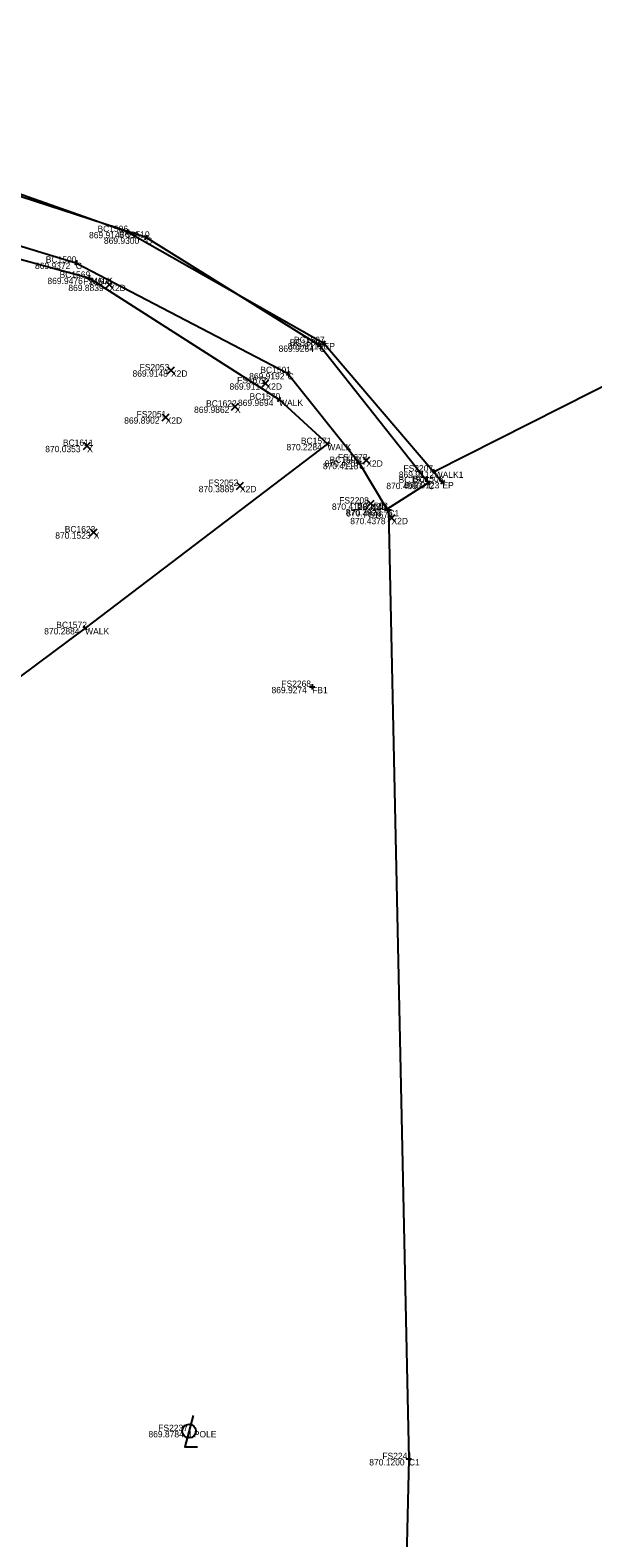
# Model space of a CAD drawing. Extents: x 1479425 to 1480294, y 379351 to 380102.
# Drawn here: x 1479711.18 to 1479716.51, y 379921.85 to 379936.13 of the extents above; entities that cross this region are included whole.
import ezdxf

# ---------------------------------------------------------------- set-up
doc = ezdxf.new("R2010")
doc.units = 0
for name, color, linetype in [('LT_X_Poles', 7, 'Continuous'), ('PV_X_Curb', 7, 'Continuous'), ('PV_X_EOP', 7, 'Continuous'), ('PV_X_Walk', 7, 'Continuous'), ('SV_X_Random_Point', 7, 'Continuous'), ('SV_X_Shot_Marker', 7, 'Continuous'), ('SV_X_Text_Comment', 7, 'Continuous'), ('SV_X_Text_Elevation', 7, 'Continuous'), ('SV_X_Text_Name', 7, 'Continuous')]:
    doc.layers.add(name, color=color, linetype=linetype)

msp = doc.modelspace()

# ---------------------------------------------------------------- linework, layer by layer
at = {"layer": 'LT_X_Poles'}
msp.add_lwpolyline([(1479712.727, 379923.013), (1479712.649, 379922.714), (1479712.767, 379922.714)], dxfattribs=at)
msp.add_circle((1479712.688, 379922.865), 0.065, dxfattribs=at)
at = {"layer": 'PV_X_Curb'}
for points in [[(1479714.562, 379931.597), (1479714.954, 379931.846), (1479713.923, 379933.146), (1479712.281, 379934.169), (1479710.424, 379934.773), (1479708.769, 379934.79), (1479708.11, 379934.798), (1479707.065, 379934.215), (1479706.4, 379933.843), (1479705.682, 379933.059), (1479703.005, 379930.335), (1479700.421, 379927.502), (1479698.116, 379923.793), (1479697.054, 379921.447), (1479696.317, 379919.513), (1479695.811, 379917.681), (1479695.461, 379914.266), (1479695.292, 379911.66), (1479695.283, 379911.471), (1479695.51, 379908.764), (1479695.652, 379906.806)], [(1479696.734, 379903.723), (1479696.078, 379906.871), (1479695.857, 379909.367), (1479695.679, 379911.575), (1479695.63, 379911.718), (1479695.729, 379913.104), (1479695.978, 379915.675), (1479696.198, 379917.494), (1479696.642, 379919.385), (1479697.412, 379921.373), (1479698.591, 379923.939), (1479699.838, 379926.058), (1479700.67, 379927.184), (1479703.372, 379930.269), (1479706.251, 379933.059), (1479706.672, 379933.535), (1479707.045, 379933.739), (1479707.413, 379933.924), (1479708.304, 379934.333), (1479710.149, 379934.374), (1479711.615, 379933.931), (1479713.621, 379932.885), (1479714.299, 379932.035), (1479714.562, 379931.597)], [(1479714.576, 379931.587), (1479714.771, 379922.599), (1479714.229, 379900.013), (1479714.491, 379898.192), (1479715.218, 379896.002), (1479717.036, 379893.796), (1479731.944, 379880.013), (1479745.709, 379867.308), (1479763.187, 379850.751), (1479775.061, 379839.578), (1479781.928, 379833.121), (1479783.777, 379830.713), (1479784.214, 379828.705), (1479783.141, 379825.906)]]:
    msp.add_lwpolyline(points, dxfattribs=at)
at = {"layer": 'PV_X_EOP'}
msp.add_lwpolyline([(1479708.075, 379934.808), (1479710.378, 379934.833), (1479712.105, 379934.222), (1479713.963, 379933.17), (1479715.088, 379931.853)], dxfattribs=at)
at = {"layer": 'PV_X_Walk'}
for points in [[(1479764.347, 379957.039), (1479747.939, 379948.677), (1479730.885, 379939.972), (1479715.015, 379931.953)], [(1479700.819, 379927.207), (1479702.519, 379929.228), (1479704.632, 379931.356), (1479706.478, 379933.039), (1479706.5, 379933.151), (1479707.222, 379933.677), (1479708.112, 379934.088), (1479708.635, 379934.285), (1479709.995, 379934.261), (1479711.737, 379933.788), (1479713.54, 379932.634), (1479713.998, 379932.214), (1479711.703, 379930.47), (1479709.843, 379929.086), (1479707.999, 379927.69), (1479707.532, 379928.002), (1479706.101, 379926.518), (1479704.906, 379925.083), (1479704.409, 379924.381), (1479704.348, 379924.281), (1479703.388, 379922.667), (1479702.617, 379921.004)]]:
    msp.add_lwpolyline(points, dxfattribs=at)
at = {"layer": 'SV_X_Random_Point'}
for p, q in [((1479711.899, 379933.688), (1479711.965, 379933.755)), ((1479711.899, 379933.755), (1479711.965, 379933.688)), ((1479712.484, 379932.878), (1479712.55, 379932.945)), ((1479712.484, 379932.945), (1479712.55, 379932.878)), ((1479713.379, 379932.754), (1479713.445, 379932.821)), ((1479713.379, 379932.821), (1479713.445, 379932.754)), ((1479713.09, 379932.535), (1479713.157, 379932.601)), ((1479713.09, 379932.601), (1479713.157, 379932.535)), ((1479712.433, 379932.433), (1479712.499, 379932.499)), ((1479712.433, 379932.499), (1479712.499, 379932.433)), ((1479711.688, 379932.163), (1479711.755, 379932.23)), ((1479711.688, 379932.23), (1479711.755, 379932.163)), ((1479714.334, 379932.026), (1479714.4, 379932.093)), ((1479714.334, 379932.093), (1479714.4, 379932.026)), ((1479713.137, 379931.784), (1479713.203, 379931.851)), ((1479713.137, 379931.851), (1479713.203, 379931.784)), ((1479714.374, 379931.617), (1479714.44, 379931.683)), ((1479714.374, 379931.683), (1479714.44, 379931.617)), ((1479714.573, 379931.48), (1479714.639, 379931.547)), ((1479714.573, 379931.547), (1479714.639, 379931.48)), ((1479711.752, 379931.344), (1479711.818, 379931.411)), ((1479711.752, 379931.411), (1479711.818, 379931.344))]:
    msp.add_line(p, q, dxfattribs=at)
at = {"layer": 'SV_X_Shot_Marker'}
for p, q in [((1479712.081, 379934.23), (1479712.128, 379934.213)), ((1479712.113, 379934.245), (1479712.096, 379934.198)), ((1479712.105, 379934.222), (1479712.105, 379934.222)), ((1479712.302, 379934.156), (1479712.26, 379934.182)), ((1479712.268, 379934.148), (1479712.294, 379934.19)), ((1479712.281, 379934.169), (1479712.281, 379934.169)), ((1479711.592, 379933.938), (1479711.639, 379933.924)), ((1479711.623, 379933.955), (1479711.608, 379933.907)), ((1479711.615, 379933.931), (1479711.615, 379933.931)), ((1479711.713, 379933.794), (1479711.762, 379933.781)), ((1479711.744, 379933.812), (1479711.731, 379933.763)), ((1479711.737, 379933.788), (1479711.737, 379933.788)), ((1479713.941, 379933.183), (1479713.985, 379933.158)), ((1479713.975, 379933.192), (1479713.951, 379933.149)), ((1479713.963, 379933.17), (1479713.963, 379933.17)), ((1479713.904, 379933.13), (1479713.943, 379933.161)), ((1479713.939, 379933.126), (1479713.908, 379933.165)), ((1479713.923, 379933.146), (1479713.923, 379933.146)), ((1479713.599, 379932.896), (1479713.643, 379932.873)), ((1479713.633, 379932.907), (1479713.61, 379932.863)), ((1479713.621, 379932.885), (1479713.621, 379932.885)), ((1479713.519, 379932.647), (1479713.561, 379932.621)), ((1479713.554, 379932.655), (1479713.527, 379932.613)), ((1479713.54, 379932.634), (1479713.54, 379932.634)), ((1479713.98, 379932.231), (1479714.016, 379932.197)), ((1479714.015, 379932.233), (1479713.981, 379932.196)), ((1479713.998, 379932.214), (1479713.998, 379932.214)), ((1479714.319, 379932.05), (1479714.28, 379932.019)), ((1479714.284, 379932.054), (1479714.315, 379932.015)), ((1479714.299, 379932.035), (1479714.299, 379932.035)), ((1479715.038, 379931.964), (1479714.993, 379931.941)), ((1479715.027, 379931.93), (1479715.004, 379931.975)), ((1479715.015, 379931.953), (1479715.015, 379931.953)), ((1479714.932, 379931.833), (1479714.975, 379931.86)), ((1479714.94, 379931.868), (1479714.967, 379931.825)), ((1479714.954, 379931.846), (1479714.954, 379931.846)), ((1479715.107, 379931.869), (1479715.069, 379931.836)), ((1479715.072, 379931.872), (1479715.105, 379931.834)), ((1479715.088, 379931.853), (1479715.088, 379931.853)), ((1479714.583, 379931.61), (1479714.54, 379931.584)), ((1479714.549, 379931.619), (1479714.575, 379931.576)), ((1479714.575, 379931.612), (1479714.576, 379931.562)), ((1479714.601, 379931.587), (1479714.551, 379931.586)), ((1479714.562, 379931.597), (1479714.562, 379931.597)), ((1479714.576, 379931.587), (1479714.576, 379931.587)), ((1479711.723, 379930.485), (1479711.684, 379930.455)), ((1479711.719, 379930.45), (1479711.688, 379930.49)), ((1479711.703, 379930.47), (1479711.703, 379930.47)), ((1479713.829, 379929.913), (1479713.879, 379929.913)), ((1479713.854, 379929.938), (1479713.854, 379929.888)), ((1479713.854, 379929.913), (1479713.854, 379929.913)), ((1479714.77, 379922.624), (1479714.772, 379922.574)), ((1479714.796, 379922.599), (1479714.746, 379922.598)), ((1479714.771, 379922.599), (1479714.771, 379922.599))]:
    msp.add_line(p, q, dxfattribs=at)

# ---------------------------------------------------------------- texts
at = {"layer": 'SV_X_Text_Comment'}
for s, p in [('EP', (1479712.105, 379934.162)), ('C', (1479712.281, 379934.109)), ('C', (1479711.615, 379933.871)), ('WALK', (1479711.737, 379933.728)), ('X2D', (1479711.932, 379933.662)), ('EP', (1479713.963, 379933.11)), ('C', (1479713.923, 379933.086)), ('X2D', (1479712.517, 379932.851)), ('C', (1479713.621, 379932.825)), ('X2D', (1479713.412, 379932.728)), ('WALK', (1479713.54, 379932.574)), ('X2D', (1479712.466, 379932.406)), ('X', (1479713.123, 379932.508)), ('X', (1479711.722, 379932.136)), ('WALK', (1479713.998, 379932.154)), ('C', (1479714.299, 379931.975)), ('X2D', (1479714.367, 379931.999)), ('WALK1', (1479715.015, 379931.893)), ('X2D', (1479713.17, 379931.757)), ('C', (1479714.954, 379931.786)), ('EP', (1479715.088, 379931.793)), ('X2D', (1479714.407, 379931.59)), ('C', (1479714.562, 379931.537)), ('C1', (1479714.576, 379931.527)), ('X2D', (1479714.606, 379931.454)), ('X', (1479711.785, 379931.317)), ('WALK', (1479711.703, 379930.41)), ('FB1', (1479713.854, 379929.853)), ('LPOLE', (1479712.688, 379922.805)), ('C1', (1479714.771, 379922.539))]:
    msp.add_text(s, height=0.06, dxfattribs=at).set_placement(p)
at = {"layer": 'SV_X_Text_Elevation'}
for s, p in [('869.9147', (1479711.74, 379934.162)), ('869.9300', (1479711.881, 379934.109)), ('869.9372', (1479711.228, 379933.871)), ('869.9476', (1479711.346, 379933.728)), ('869.8839', (1479711.544, 379933.662)), ('869.9115', (1479713.622, 379933.11)), ('869.9264', (1479713.536, 379933.086)), ('869.9148', (1479712.152, 379932.851)), ('869.9192', (1479713.257, 379932.825)), ('869.9117', (1479713.071, 379932.728)), ('869.9694', (1479713.151, 379932.574)), ('869.8902', (1479712.073, 379932.406)), ('869.9862', (1479712.735, 379932.508)), ('870.0353', (1479711.325, 379932.136)), ('870.2284', (1479713.611, 379932.154)), ('870.4118', (1479713.956, 379931.975)), ('870.4207', (1479713.972, 379931.999)), ('869.9112', (1479714.675, 379931.893)), ('870.3889', (1479712.779, 379931.757)), ('870.4093', (1479714.557, 379931.786)), ('869.9123', (1479714.725, 379931.793)), ('870.4128', (1479714.041, 379931.59)), ('870.3922', (1479714.172, 379931.537)), ('870.4076', (1479714.177, 379931.527)), ('870.4378', (1479714.215, 379931.454)), ('870.1523', (1479711.42, 379931.317)), ('870.2884', (1479711.315, 379930.41)), ('869.9274', (1479713.469, 379929.853)), ('869.8784', (1479712.303, 379922.805)), ('870.1200', (1479714.395, 379922.539))]:
    msp.add_text(s, height=0.06, dxfattribs=at).set_placement(p)
at = {"layer": 'SV_X_Text_Name'}
for s, p in [('BC1506', (1479711.82, 379934.222)), ('BC1510', (1479712.024, 379934.169)), ('BC1500', (1479711.33, 379933.931)), ('BC1569', (1479711.461, 379933.788)), ('FS1671', (1479711.685, 379933.722)), ('BC1509', (1479713.642, 379933.146)), ('BC1507', (1479713.682, 379933.17)), ('FS2053', (1479712.219, 379932.911)), ('BC1501', (1479713.363, 379932.885)), ('FS1672', (1479713.143, 379932.788)), ('BC1622', (1479712.849, 379932.568)), ('BC1570', (1479713.261, 379932.634)), ('FS2051', (1479712.191, 379932.466)), ('BC1611', (1479711.492, 379932.196)), ('BC1571', (1479713.747, 379932.214)), ('BC1502', (1479714.019, 379932.035)), ('FS1673', (1479714.098, 379932.059)), ('BC1504', (1479714.673, 379931.846)), ('FS2207', (1479714.719, 379931.953)), ('BC1508', (1479714.807, 379931.853)), ('FS2052', (1479712.873, 379931.817)), ('FS2208', (1479714.11, 379931.65)), ('FS2240', (1479714.279, 379931.587)), ('BC1503', (1479714.281, 379931.597)), ('FS1674', (1479714.337, 379931.514)), ('BC1623', (1479711.51, 379931.377)), ('BC1572', (1479711.43, 379930.47)), ('FS2268', (1479713.562, 379929.913)), ('FS2237', (1479712.396, 379922.865)), ('FS2241', (1479714.519, 379922.599))]:
    msp.add_text(s, height=0.06, dxfattribs=at).set_placement(p)

doc.saveas('drawing.dxf')
